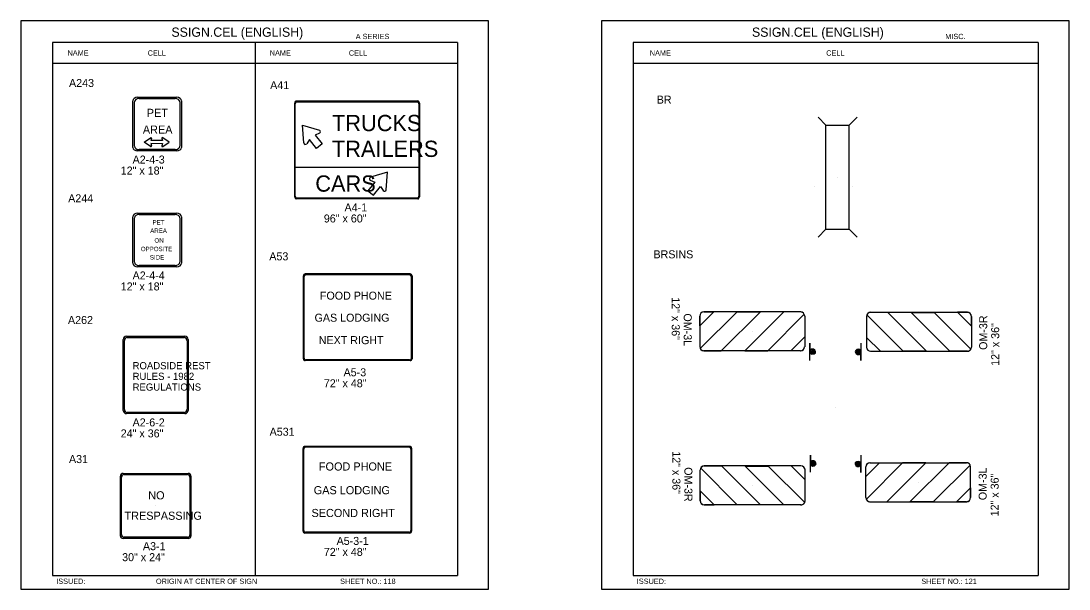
# Model space of a CAD drawing. Extents: x -5299 to 22597, y -19549 to -1808.
# Drawn here: x -4301 to -2729, y -14722 to -13870 of the extents above; entities that cross this region are included whole.
import ezdxf

# ---------------------------------------------------------------- set-up
doc = ezdxf.new("R2010")
doc.units = 0
for name, color, linetype in [('Level 1', 7, 'Continuous'), ('Level 2', 7, 'Continuous'), ('Level 3', 7, 'Continuous'), ('Level 60', 7, 'Continuous')]:
    doc.layers.add(name, color=color, linetype=linetype)

msp = doc.modelspace()

# ---------------------------------------------------------------- linework, layer by layer
at = {"layer": 'Level 1'}
for p, q in [((-3646, -13902), (-4253, -13902)), ((-4253, -13902), (-4253, -14702)), ((-3949.5, -13902), (-3949.5, -14702)), ((-3646, -13902), (-3646, -14702)), ((-2775.3, -13902), (-3382.3, -13902)), ((-3382.3, -13902), (-3382.3, -14702)), ((-2775.3, -13902), (-2775.3, -14702)), ((-3646, -13933.7), (-4253, -13933.7)), ((-2775.3, -13933.7), (-3382.3, -13933.7)), ((-4125.6, -13984.4), (-4067.1, -13984.4)), ((-4123.4, -13986.4), (-4069.2, -13986.4)), ((-4132.9, -14059.5), (-4132.9, -13989.8)), ((-4130.1, -14057.9), (-4130.1, -13991.4)), ((-4062.5, -13991.4), (-4062.5, -14057.9)), ((-4059.7, -13989.8), (-4059.7, -14059.5)), ((-3890, -14133.6), (-3890, -13993.2)), ((-3889.1, -14132.8), (-3889.1, -13994.1)), ((-3887.6, -13989.9), (-3705.4, -13989.9)), ((-3887, -13991.1), (-3706.1, -13991.1)), ((-3704, -13994.1), (-3704, -14132.8)), ((-3703, -13993.2), (-3703, -14133.6)), ((-3093.3, -14026.3), (-3105.2, -14014.4)), ((-3058.6, -14026.3), (-3046.7, -14014.4)), ((-4096.3, -14024.6), (-4096.3, -14024.6)), ((-3876.3, -14052.9), (-3878.3, -14026.3)), ((-3878.3, -14026.3), (-3852.8, -14033.8)), ((-3093.3, -14182.4), (-3093.3, -14026.3)), ((-3093.3, -14026.3), (-3058.6, -14026.3)), ((-3058.6, -14182.4), (-3058.6, -14026.3)), ((-4115.8, -14051.6), (-4106.3, -14045.1)), ((-4104.8, -14046.2), (-4105.7, -14049.3)), ((-4088.4, -14049.3), (-4105.7, -14049.3)), ((-4089.3, -14046.2), (-4088.4, -14049.3)), ((-4078.4, -14051.6), (-4087.8, -14045.1)), ((-3867.9, -14047.9), (-3872, -14054)), ((-3857.3, -14061), (-3867.9, -14047.9)), ((-3852.6, -14038.3), (-3859.5, -14041.1)), ((-3859.5, -14041.1), (-3848.9, -14054.2)), ((-4067.1, -14064.9), (-4125.6, -14064.9)), ((-4069.2, -14062.9), (-4123.4, -14062.9)), ((-4106.3, -14058.2), (-4115.8, -14051.6)), ((-4105.7, -14053.9), (-4104.8, -14057)), ((-4088.4, -14054), (-4105.7, -14053.9)), ((-4088.4, -14053.9), (-4089.3, -14057)), ((-4087.8, -14058.1), (-4078.4, -14051.6)), ((-3848.9, -14054.2), (-3857.3, -14061)), ((-3889.1, -14089), (-3703.9, -14089)), ((-3750.9, -14096.7), (-3776.5, -14104.2)), ((-3752.9, -14123.3), (-3750.9, -14096.7)), ((-3769.7, -14111.5), (-3780.3, -14124.6)), ((-3776.6, -14108.7), (-3769.7, -14111.5)), ((-3076, -14104.2), (-3076, -14104.2)), ((-3780.3, -14124.6), (-3771.9, -14131.4)), ((-3771.9, -14131.4), (-3761.3, -14118.3)), ((-3761.3, -14118.3), (-3757.2, -14124.4)), ((-3111.1, -14117.8), (-3111.1, -14117.8)), ((-3054.1, -14117.8), (-3054.1, -14117.8)), ((-3705.4, -14136.9), (-3887.6, -14136.9)), ((-3706.1, -14135.7), (-3887, -14135.7)), ((-4125.6, -14158.2), (-4067.1, -14158.2)), ((-4123.4, -14160.2), (-4069.2, -14160.2)), ((-4132.9, -14233.3), (-4132.9, -14163.6)), ((-4130.1, -14231.7), (-4130.1, -14165.2)), ((-4062.5, -14165.2), (-4062.5, -14231.7)), ((-4059.7, -14163.6), (-4059.7, -14233.3)), ((-3105.2, -14194.4), (-3093.3, -14182.4)), ((-3093.3, -14182.4), (-3058.6, -14182.4)), ((-3046.7, -14194.4), (-3058.6, -14182.4)), ((-4096.3, -14198.4), (-4096.3, -14198.4)), ((-4067.1, -14238.7), (-4125.6, -14238.7)), ((-4069.2, -14236.7), (-4123.4, -14236.7)), ((-3876.9, -14376.6), (-3876.9, -14252.4)), ((-3875.9, -14375.7), (-3875.9, -14253.5)), ((-3716.8, -14249.5), (-3874.2, -14249.5)), ((-3717.6, -14250.8), (-3873.4, -14250.8)), ((-3715.1, -14253.4), (-3715.1, -14375.7)), ((-3714, -14252.2), (-3714, -14376.6)), ((-3795.5, -14314.5), (-3795.5, -14314.5)), ((-3261.5, -14306.3), (-3282.5, -14327.4)), ((-3282.5, -14312.6), (-3282.5, -14358.6)), ((-3282.5, -14327.4), (-3282.5, -14312.8)), ((-3226.9, -14306.6), (-3281.8, -14361.4)), ((-3276.6, -14306.3), (-3261.5, -14306.3)), ((-3131, -14306.3), (-3276.3, -14306.3)), ((-3250.3, -14364.6), (-3192.1, -14306.6)), ((-3192.1, -14306.6), (-3226.9, -14306.6)), ((-3157.2, -14306.6), (-3215.2, -14364.6)), ((-3180.4, -14364.6), (-3125.8, -14310)), ((-3132, -14306.3), (-3157.2, -14306.6)), ((-3125.2, -14312.6), (-3125.2, -14358.6)), ((-3032.5, -14313.2), (-3032.5, -14359.2)), ((-2977.4, -14365.2), (-3032, -14310.6)), ((-3026.8, -14307), (-2881.4, -14307)), ((-3025.7, -14307), (-3000.5, -14307.2)), ((-3000.5, -14307.2), (-2942.5, -14365.2)), ((-2965.7, -14307.2), (-2930.8, -14307.2)), ((-2907.4, -14365.2), (-2965.7, -14307.2)), ((-2930.8, -14307.2), (-2876, -14362.1)), ((-2896.3, -14307), (-2875.2, -14328)), ((-2881.2, -14307), (-2896.3, -14307)), ((-2875.2, -14313.2), (-2875.2, -14359.2)), ((-2875.2, -14328), (-2875.2, -14313.5)), ((-4147.3, -14454.1), (-4147.3, -14347.9)), ((-4145.4, -14452.7), (-4145.4, -14349.3)), ((-4142.4, -14343), (-4054.6, -14343)), ((-4141, -14344.8), (-4056, -14344.8)), ((-4051.5, -14349.2), (-4051.5, -14452.7)), ((-4049.7, -14347.9), (-4049.7, -14454.1)), ((-3203.8, -14335.6), (-3203.8, -14335.6)), ((-3146, -14364.8), (-3125.2, -14344)), ((-3125.2, -14344), (-3125.2, -14358.6)), ((-3011.7, -14365.5), (-3032.5, -14344.7)), ((-3032.5, -14344.7), (-3032.5, -14359.2)), ((-2954, -14336.2), (-2954, -14336.2)), ((-3276.6, -14364.8), (-3250.3, -14364.6)), ((-3131.5, -14364.8), (-3276.3, -14364.8)), ((-3215.2, -14364.6), (-3180.4, -14364.6)), ((-3131.7, -14364.8), (-3146, -14364.8)), ((-3125.2, -14358.6), (-3125.2, -14358.8)), ((-3032.5, -14359.2), (-3032.5, -14359.5)), ((-3026.3, -14365.5), (-2881.4, -14365.5)), ((-3026, -14365.5), (-3011.7, -14365.5)), ((-2942.5, -14365.2), (-2977.4, -14365.2)), ((-2881.2, -14365.5), (-2907.4, -14365.2)), ((-3716.8, -14379.5), (-3874.2, -14379.5)), ((-3717.6, -14378.4), (-3873.4, -14378.4)), ((-4054.6, -14459), (-4142.4, -14459)), ((-4056, -14457.2), (-4141, -14457.2)), ((-3078.8, -14450.2), (-3078.8, -14450.2)), ((-3877.5, -14635.3), (-3877.5, -14511.1)), ((-3876.5, -14634.4), (-3876.5, -14512.2)), ((-3717.4, -14508.1), (-3874.8, -14508.1)), ((-3718.2, -14509.5), (-3874, -14509.5)), ((-3715.7, -14512.2), (-3715.7, -14634.4)), ((-3714.7, -14510.9), (-3714.7, -14635.3)), ((-3276, -14537.4), (-3249.7, -14537.7)), ((-3130.9, -14537.4), (-3275.7, -14537.4)), ((-3249.7, -14537.7), (-3191.5, -14595.7)), ((-3156.6, -14595.7), (-3214.6, -14537.7)), ((-3214.6, -14537.7), (-3179.8, -14537.7)), ((-3179.8, -14537.7), (-3125.2, -14592.3)), ((-3131.2, -14537.4), (-3145.5, -14537.4)), ((-3145.5, -14537.4), (-3124.7, -14558.2)), ((-3012.9, -14532.8), (-3033.7, -14553.6)), ((-2978.6, -14533.1), (-3033.2, -14587.7)), ((-3027.4, -14532.8), (-2882.6, -14532.8)), ((-3027.2, -14532.8), (-3012.9, -14532.8)), ((-3001.7, -14591), (-2943.7, -14533.1)), ((-2943.7, -14533.1), (-2978.6, -14533.1)), ((-2908.6, -14533.1), (-2966.9, -14591)), ((-2932, -14591), (-2877.2, -14536.2)), ((-2882.4, -14532.8), (-2908.6, -14533.1)), ((-4151.3, -14642.9), (-4151.3, -14553)), ((-4147.1, -14548.8), (-4049.8, -14548.8)), ((-4145.9, -14550.6), (-4050.8, -14550.6)), ((-4145.8, -14550.4), (-4051, -14550.4)), ((-4045.6, -14553), (-4045.6, -14642.8)), ((-3282, -14589.7), (-3282, -14543.7)), ((-3226.3, -14595.7), (-3281.2, -14540.8)), ((-3124.7, -14543.7), (-3124.7, -14543.4)), ((-3124.7, -14589.7), (-3124.7, -14543.7)), ((-3124.7, -14558.2), (-3124.7, -14543.7)), ((-3033.7, -14539), (-3033.7, -14538.8)), ((-3033.7, -14585.1), (-3033.7, -14539)), ((-3033.7, -14553.6), (-3033.7, -14539)), ((-2876.4, -14585.1), (-2876.4, -14539)), ((-4149.7, -14640.7), (-4149.7, -14554.3)), ((-4047.2, -14554.3), (-4047.2, -14640.7)), ((-3203.2, -14566.7), (-3203.2, -14566.7)), ((-2955.2, -14562), (-2955.2, -14562)), ((-3796.1, -14573.2), (-3796.1, -14573.2)), ((-3260.9, -14595.9), (-3282, -14574.9)), ((-3282, -14574.9), (-3282, -14589.4)), ((-2897.4, -14591.3), (-2876.4, -14570.2)), ((-2876.4, -14570.2), (-2876.4, -14584.8)), ((-4098.4, -14597.5), (-4098.4, -14597.5)), ((-3276, -14595.9), (-3260.9, -14595.9)), ((-3130.4, -14595.9), (-3275.7, -14595.9)), ((-3191.5, -14595.7), (-3226.3, -14595.7)), ((-3131.4, -14595.9), (-3156.6, -14595.7)), ((-3028, -14591.3), (-2882.6, -14591.3)), ((-3026.9, -14591.3), (-3001.7, -14591)), ((-2966.9, -14591), (-2932, -14591)), ((-2882.4, -14591.3), (-2897.4, -14591.3)), ((-4049.8, -14646.4), (-4147.1, -14646.4)), ((-4051, -14644.6), (-4145.8, -14644.6)), ((-3717.4, -14638.2), (-3874.8, -14638.2)), ((-3718.2, -14637.1), (-3874, -14637.1)), ((-4253, -14702), (-3646, -14702)), ((-3382.3, -14702), (-2775.3, -14702))]:
    msp.add_line(p, q, dxfattribs=at)
for centre, radius, start, end in [((-3853.6, -14036.1), 2.4, 293.1482, 70.9919), ((-4105.8, -14046), 1.03, 344.1482, 121.9919), ((-4088.4, -14046), 1.03, 58.0081, 195.8518), ((-4105.8, -14057.3), 1.02, 236.5086, 17.4189), ((-4088.4, -14057.3), 1.02, 162.5811, 303.4914), ((-3874, -14052.7), 2.36, 185.5086, 326.4189), ((-3775.6, -14106.5), 2.4, 109.0081, 246.8518), ((-3755.2, -14123.1), 2.36, 213.5811, 354.4914), ((-3276.3, -14312.6), 6.24, 90, 180), ((-3276.3, -14312.5), 6.13, 93.0907, 183.0907), ((-3131.6, -14313), 6.55, 26.6664, 93.2943), ((-3131.6, -14312.6), 6.36, 0.5054, 90.5054), ((-3026.1, -14313.3), 6.36, 89.4946, 179.4946), ((-3026.1, -14313.6), 6.55, 86.7057, 153.3336), ((-2881.4, -14313.2), 6.24, 0, 90), ((-2881.4, -14313.2), 6.13, 356.9093, 86.9093), ((-4142.4, -14347.9), 4.88, 90, 180), ((-4141, -14349.3), 4.47, 90, 180), ((-4056, -14349.3), 4.47, 0, 90), ((-4054.6, -14347.9), 4.88, 0, 90), ((-3276.3, -14358.6), 6.24, 180, 270), ((-3276.5, -14358.9), 5.86, 206.4031, 269.2905), ((-3131.6, -14358.5), 6.28, 268.6953, 358.1007), ((-3131.5, -14358.6), 6.24, 270, 0), ((-3026.3, -14359.2), 6.24, 180, 270), ((-3026.2, -14359.2), 6.28, 181.8993, 271.3047), ((-2881.4, -14359.2), 6.24, 270, 0), ((-2881.2, -14359.5), 5.86, 270.7095, 333.5969), ((-4142.4, -14454.1), 4.88, 180, 270), ((-4141, -14452.7), 4.47, 180, 270), ((-4056, -14452.7), 4.47, 270, 0), ((-4054.6, -14454.1), 4.88, 270, 0), ((-3275.7, -14543.6), 6.24, 90, 180), ((-3275.9, -14543.3), 5.86, 90.7095, 153.5969), ((-3131, -14543.7), 6.28, 1.8993, 91.3047), ((-3130.9, -14543.6), 6.24, 0, 90), ((-3027.4, -14539), 6.24, 90, 180), ((-3027.3, -14539.1), 6.28, 88.6953, 178.1007), ((-2882.6, -14539), 6.24, 0, 90), ((-2882.4, -14538.7), 5.86, 26.4031, 89.2905), ((-4147.1, -14553), 4.23, 90, 180), ((-4145.8, -14554.3), 3.88, 90, 180), ((-4051, -14554.3), 3.88, 0, 90), ((-4049.8, -14553), 4.23, 0, 90), ((-3027.3, -14585), 6.36, 180.5054, 270.5054), ((-2882.6, -14585), 6.24, 270, 0), ((-2882.6, -14585.1), 6.13, 273.0907, 3.0907), ((-3275.7, -14589.7), 6.24, 180, 270), ((-3275.8, -14589.7), 6.13, 176.9093, 266.9093), ((-3131, -14589.3), 6.55, 266.7057, 333.3336), ((-3131, -14589.6), 6.36, 269.4946, 359.4946), ((-3027.3, -14584.6), 6.55, 206.6664, 273.2943), ((-4147.1, -14642.2), 4.23, 180, 270), ((-4145.8, -14640.4), 3.88, 180, 270), ((-4051, -14640.7), 3.88, 270, 0), ((-4049.8, -14642.2), 4.23, 270, 0)]:
    msp.add_arc(centre, radius, start, end, dxfattribs=at)
for centre, major_axis, ratio, start_param, end_param in [((-4125.6, -13989.8), (-7.31, 0), 0.7337, 4.712389, 6.283185), ((-4123.4, -13991.4), (-6.77, 0), 0.7337, 4.712389, 6.283185), ((-4069.2, -13991.4), (-6.77, 0), 0.7337, 3.141593, 4.712389), ((-4067.1, -13989.8), (-7.31, 0), 0.7337, 3.141593, 4.712389), ((-3887.6, -13993.2), (0, -3.25), 0.71875, 3.141593, 4.712389), ((-3887, -13994.1), (0, -3.01), 0.71875, 3.141593, 4.712389), ((-3706.1, -13994.1), (0, 3.01), 0.71875, 4.712389, 6.283185), ((-3705.4, -13993.2), (0, 3.25), 0.71875, 4.712389, 6.283185), ((-4125.6, -14059.5), (-7.31, 0), 0.7337, 0, 1.570796), ((-4123.4, -14057.9), (6.77, 0), 0.7337, 3.141593, 4.712389), ((-4069.2, -14057.9), (6.77, 0), 0.7337, 4.712389, 6.283185), ((-4067.1, -14059.5), (7.31, 0), 0.7337, 4.712389, 6.283185), ((-3887.6, -14133.6), (0, -3.25), 0.71875, 4.712389, 6.283185), ((-3887, -14132.7), (0, -3.01), 0.71875, 4.712389, 6.283185), ((-3706.1, -14132.7), (0, 3.01), 0.71875, 3.141593, 4.712389), ((-3705.4, -14133.6), (0, 3.25), 0.71875, 3.141593, 4.712389), ((-4125.6, -14163.6), (-7.31, 0), 0.7337, 4.712389, 6.283185), ((-4123.4, -14165.2), (-6.77, 0), 0.7337, 4.712389, 6.283185), ((-4069.2, -14165.2), (-6.77, 0), 0.7337, 3.141593, 4.712389), ((-4067.1, -14163.6), (-7.31, 0), 0.7337, 3.141593, 4.712389), ((-4125.6, -14233.3), (-7.31, 0), 0.7337, 0, 1.570796), ((-4123.4, -14231.7), (6.77, 0), 0.7337, 3.141593, 4.712389), ((-4069.2, -14231.7), (6.77, 0), 0.7337, 4.712389, 6.283185), ((-4067.1, -14233.3), (7.31, 0), 0.7337, 4.712389, 6.283185), ((-3874.2, -14252.4), (0, -2.93), 0.9275, 3.141593, 4.712389), ((-3873.3, -14253.5), (0, -2.71), 0.9275, 3.141593, 4.712389), ((-3717.6, -14253.5), (0, 2.71), 0.9275, 4.712389, 6.283185), ((-3716.8, -14252.4), (0, 2.93), 0.9275, 4.712389, 6.283185), ((-3874.2, -14376.6), (0, -2.93), 0.9275, 4.712389, 6.283185), ((-3873.4, -14375.7), (0, -2.71), 0.9275, 4.712389, 6.283185), ((-3717.6, -14375.7), (0, 2.71), 0.9275, 3.141593, 4.712389), ((-3716.8, -14376.6), (0, 2.93), 0.9275, 3.141593, 4.712389), ((-3874.8, -14511.1), (0, -2.93), 0.9275, 3.141593, 4.712389), ((-3874, -14512.2), (0, -2.71), 0.9275, 3.141593, 4.712389), ((-3718.2, -14512.2), (0, 2.71), 0.9275, 4.712389, 6.283185), ((-3717.4, -14511.1), (0, 2.93), 0.9275, 4.712389, 6.283185), ((-3874.8, -14635.3), (0, -2.93), 0.9275, 4.712389, 6.283185), ((-3874, -14634.4), (0, -2.71), 0.9275, 4.712389, 6.283185), ((-3718.2, -14634.4), (0, 2.71), 0.9275, 3.141593, 4.712389), ((-3717.4, -14635.3), (0, 2.93), 0.9275, 3.141593, 4.712389)]:
    msp.add_ellipse(centre, major_axis=major_axis, ratio=ratio, start_param=start_param, end_param=end_param, dxfattribs=at)
at = {"layer": 'Level 2'}
for points in [[(-3117.3, -14379.3), (-3117.3, -14353.3), (-3117.3, -14365.9), (-3116.4, -14368.6), (-3114.3, -14370), (-3111.2, -14369.5), (-3109, -14367.8), (-3108.9, -14366.2), (-3110.1, -14363.6), (-3112.1, -14362.2), (-3115.1, -14362.3), (-3116.8, -14364), (-3116.4, -14366.8), (-3113.9, -14368.9), (-3111.8, -14368.2), (-3110.4, -14367), (-3111.2, -14364.3), (-3113.7, -14363.2), (-3115.1, -14364.8), (-3115.1, -14366.8), (-3113.9, -14367.6), (-3112.3, -14367.5), (-3112.1, -14366.1), (-3113.1, -14365.3), (-3114, -14365.3), (-3114.3, -14366.2), (-3113.4, -14366.4)], [(-3040.9, -14353.1), (-3040.9, -14379.2), (-3040.9, -14366.5), (-3041.8, -14363.9), (-3043.9, -14362.5), (-3047, -14362.9), (-3049.2, -14364.7), (-3049.3, -14366.2), (-3048.1, -14368.9), (-3046, -14370.3), (-3043.1, -14370.1), (-3041.4, -14368.4), (-3041.8, -14365.6), (-3044.3, -14363.6), (-3046.4, -14364.2), (-3047.8, -14365.4), (-3047, -14368.1), (-3044.5, -14369.2), (-3043.1, -14367.6), (-3043.1, -14365.6), (-3044.3, -14364.8), (-3045.9, -14365), (-3046, -14366.4), (-3045.1, -14367.1), (-3044.2, -14367.1), (-3043.9, -14366.2), (-3044.8, -14366.1)], [(-3116.6, -14547.1), (-3116.6, -14521.1), (-3116.6, -14533.7), (-3115.6, -14536.3), (-3113.6, -14537.8), (-3110.5, -14537.3), (-3108.3, -14535.6), (-3108.2, -14534), (-3109.4, -14531.4), (-3111.4, -14529.9), (-3114.4, -14530.1), (-3116.1, -14531.8), (-3115.6, -14534.6), (-3113.1, -14536.7), (-3111.1, -14536), (-3109.7, -14534.8), (-3110.5, -14532.1), (-3113, -14531), (-3114.4, -14532.6), (-3114.4, -14534.6), (-3113.1, -14535.4), (-3111.6, -14535.3), (-3111.4, -14533.9), (-3112.4, -14533.1), (-3113.3, -14533.1), (-3113.6, -14534), (-3112.7, -14534.2)], [(-3041.1, -14521.4), (-3041.1, -14547.4), (-3041.1, -14534.8), (-3042.1, -14532.1), (-3044.1, -14530.7), (-3047.2, -14531.2), (-3049.4, -14532.9), (-3049.6, -14534.5), (-3048.3, -14537.1), (-3046.3, -14538.5), (-3043.3, -14538.4), (-3041.6, -14536.6), (-3042.1, -14533.8), (-3044.6, -14531.8), (-3046.6, -14532.4), (-3048, -14533.7), (-3047.2, -14536.3), (-3044.7, -14537.4), (-3043.3, -14535.9), (-3043.3, -14533.8), (-3044.6, -14533.1), (-3046.1, -14533.2), (-3046.3, -14534.6), (-3045.3, -14535.4), (-3044.4, -14535.4), (-3044.1, -14534.5), (-3045, -14534.3)]]:
    msp.add_lwpolyline(points, dxfattribs=at)
at = {"layer": 'Level 60'}
for points in [[(-4300.5, -14722.2), (-3599.5, -14722.2), (-3599.5, -13869.8), (-4300.5, -13869.8)], [(-3429.8, -14722.2), (-2728.8, -14722.2), (-2728.8, -13869.8), (-3429.8, -13869.8)]]:
    msp.add_lwpolyline(points, close=True, dxfattribs=at)

# ---------------------------------------------------------------- texts
at = {"layer": 'Level 1'}
for s, height, p in [('PET', 12.2, (-4111.8, -14013.9)), ('TRUCKS', 24.38, (-3834, -14035.2)), ('AREA', 12.2, (-4117.7, -14039)), ('TRAILERS', 24.38, (-3834.1, -14073.9)), ('CARS', 24.38, (-3859.1, -14126)), ('PET', 6.67, (-4103.3, -14175.4)), ('AREA', 6.67, (-4106.7, -14187.9)), ('ON', 6.67, (-4100.3, -14202.4)), ('OPPOSITE', 6.67, (-4120.8, -14215.3)), ('SIDE', 6.67, (-4107.2, -14227.9)), ('FOOD PHONE', 12, (-3852.2, -14288)), ('GAS LODGING', 12, (-3860.2, -14321.1)), ('NEXT RIGHT', 12, (-3853.9, -14354.8)), ('ROADSIDE REST', 10.716, (-4133.1, -14392.4)), ('RULES - 1982', 10.716, (-4133.1, -14408.4)), ('REGULATIONS', 10.714, (-4133.1, -14424.5)), ('FOOD PHONE', 12.2, (-3853.7, -14544.4)), ('GAS LODGING', 12.197, (-3861.4, -14580)), ('NO', 12.2, (-4109.6, -14587.7)), ('TRESPASSING', 12.197, (-4145.2, -14618.3)), ('SECOND RIGHT', 12.197, (-3864.8, -14614.2))]:
    msp.add_text(s, height=height, dxfattribs=at).set_placement(p)
at = {"layer": 'Level 2'}
for s, p in [('A243', (-4228.4, -13968.9)), ('A41', (-3926.8, -13972.2)), ('A244', (-4229.7, -14142)), ('A53', (-3928.1, -14229)), ('A262', (-4230, -14324.6)), ('A531', (-3927.6, -14492.2)), ('A31', (-4228.5, -14533.2))]:
    msp.add_text(s, height=12, dxfattribs=at).set_placement(p)
at = {"layer": 'Level 3'}
for s, height, p in [('SSIGN.CEL (ENGLISH)', 13.857, (-4074.9, -13893.6)), ('A SERIES', 7.92, (-3798.5, -13897.1)), ('SSIGN.CEL (ENGLISH)', 13.857, (-3204.3, -13893.6)), ('MISC.', 7.92, (-2914.4, -13897.1)), ('NAME', 7.92, (-4230.7, -13921.9)), ('CELL', 7.92, (-4110.5, -13921.9)), ('NAME', 7.92, (-3927.4, -13921.9)), ('CELL', 7.92, (-3808.8, -13921.9)), ('NAME', 7.92, (-3357.5, -13921.9)), ('CELL', 7.92, (-3093, -13921.9)), ('BR', 12, (-3347.1, -13993.9)), ('A2-4-3', 12, (-4133.1, -14083.8)), ('12" x 18"', 12, (-4150.9, -14100.3)), ('A4-1', 12, (-3815.3, -14155.7)), ('96" x 60"', 12, (-3846.3, -14172.2)), ('BRSINS', 12, (-3352, -14226)), ('A2-4-4', 12, (-4133.1, -14257.7)), ('12" x 18"', 12, (-4150.9, -14274.2)), ('A5-3', 12, (-3816.7, -14403)), ('72" x 48"', 12, (-3846.3, -14419.5)), ('A2-6-2', 12, (-4133.1, -14478.2)), ('24" x 36"', 12, (-4150.9, -14494.7)), ('A5-3-1', 12, (-3827.2, -14656)), ('A3-1', 12, (-4117.6, -14663.9)), ('72" x 48"', 12, (-3846.3, -14672.5)), ('30" x 24"', 12, (-4148.8, -14680.4)), ('ISSUED:', 7.92, (-4247.6, -14714.5)), ('ORIGIN AT CENTER OF SIGN', 7.918, (-4098.1, -14714.5)), ('SHEET NO.: 118', 7.918, (-3821.9, -14714.5)), ('ISSUED:', 7.92, (-3377, -14714.5)), ('SHEET NO.: 121', 7.918, (-2950.3, -14714.5))]:
    msp.add_text(s, height=height, dxfattribs=at).set_placement(p)
for s, rotation, p in [('12" x 36"', 270, (-3324.6, -14284.4)), ('OM-3L', 270, (-3306.6, -14308.7)), ('OM-3R', 90, (-2851.5, -14363.4)), ('12" x 36"', 90, (-2833.5, -14387.3)), ('12" x 36"', 270, (-3323.6, -14515.5)), ('OM-3R', 270, (-3305.6, -14539.4)), ('OM-3L', 90, (-2852.3, -14588.9)), ('12" x 36"', 90, (-2834.3, -14613.2))]:
    msp.add_text(s, height=12, rotation=rotation, dxfattribs=at).set_placement(p)

doc.saveas('drawing.dxf')
